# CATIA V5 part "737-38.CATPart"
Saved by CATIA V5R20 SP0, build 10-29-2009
Part number: 737-38
Definition: NONE
Nomenclature: 737-38
Source: Unknown
Description: 737-38
Bounding box of the stored display mesh (mm): x -42.5 to 33, y -42.431 to 42.431, z -47 to 30
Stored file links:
  C:\Users\Utente\Desktop\IO LAVORO\3D X SITO CF\X SITO\737\737-38.CATPart
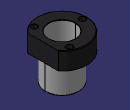
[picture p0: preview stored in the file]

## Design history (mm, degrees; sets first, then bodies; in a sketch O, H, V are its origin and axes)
Body1 "737-38" (main body)
  Solid1: solid without history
